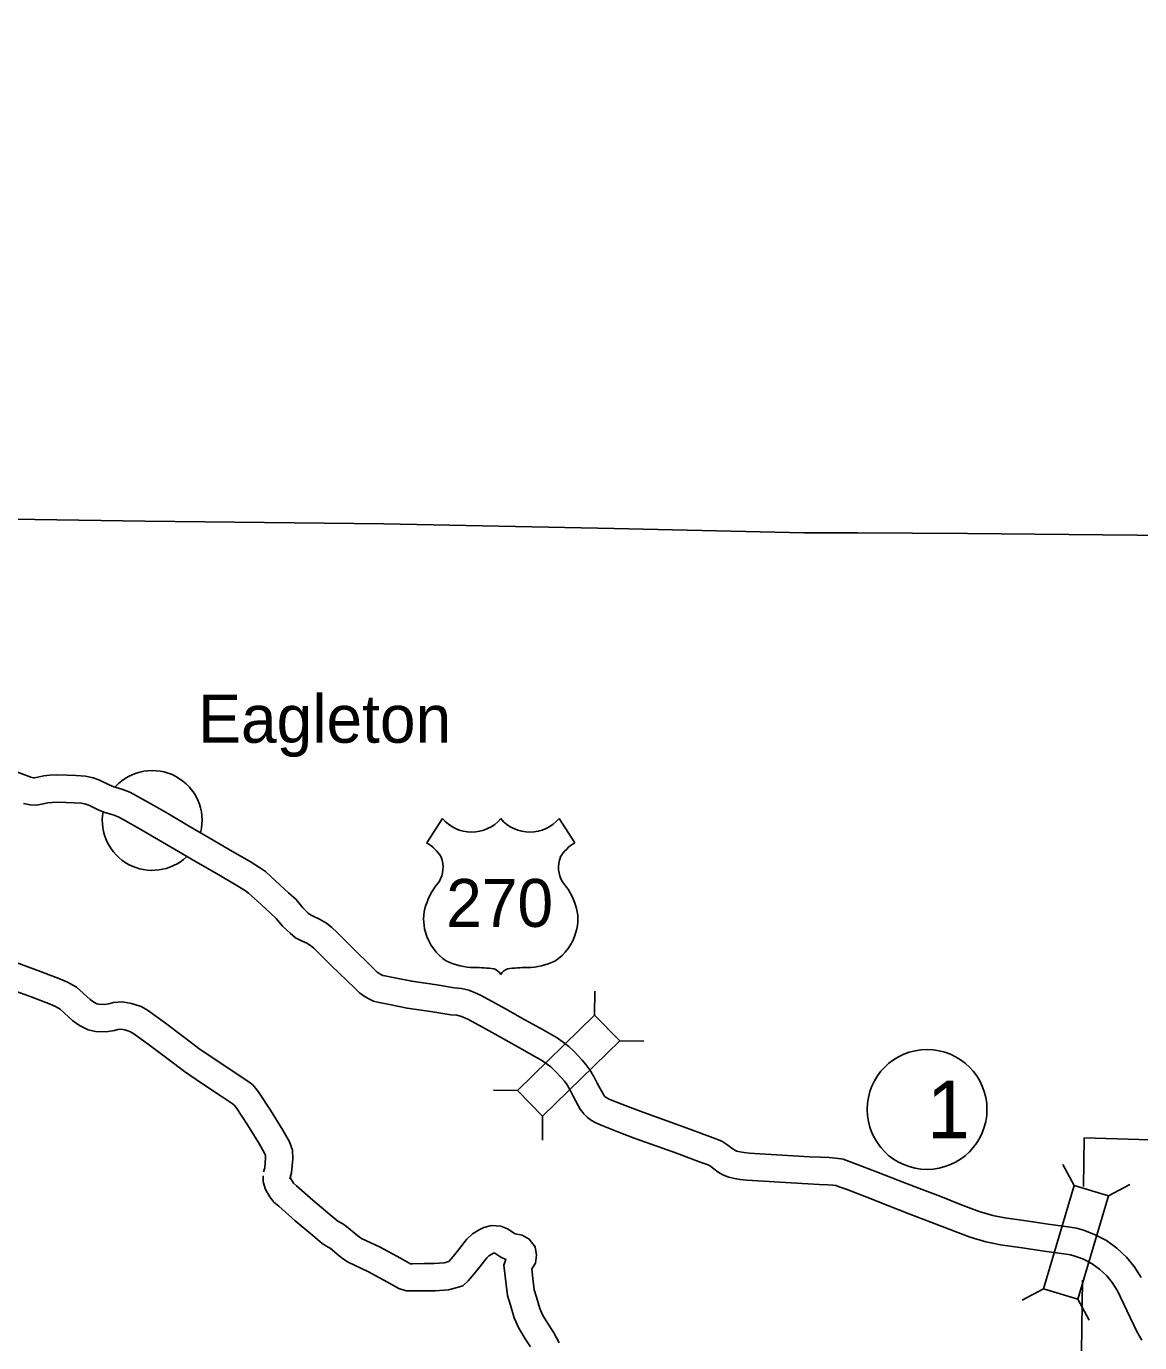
# Model space of a CAD drawing. Extents: x -939622 to -934245, y 1383184 to 1385301.
# Drawn here: x -936388.3 to -936351.49, y 1384181.69 to 1384225.19 of the extents above; entities that cross this region are included whole.
import ezdxf

# ---------------------------------------------------------------- set-up
doc = ezdxf.new("R2010")
doc.units = 0
for name, color, linetype in [('10', 7, 'Continuous'), ('15', 7, 'Continuous'), ('2', 7, 'Continuous'), ('20', 7, 'Continuous'), ('22', 7, 'Continuous'), ('24', 7, 'Continuous'), ('27', 7, 'Continuous'), ('8', 7, 'Continuous'), ('Level 2', 7, 'Continuous')]:
    doc.layers.add(name, color=color, linetype=linetype)

msp = doc.modelspace()

# ---------------------------------------------------------------- linework, layer by layer
at = {"layer": '10'}
for points in [[(-936379.586, 1384187.098), (-936379.528, 1384187.309), (-936379.489, 1384187.767), (-936379.495, 1384188.052), (-936379.602, 1384188.333), (-936379.815, 1384188.709), (-936380.231, 1384189.372), (-936380.63, 1384189.991), (-936380.808, 1384190.208), (-936380.973, 1384190.332), (-936381.326, 1384190.567), (-936382.003, 1384191.019), (-936382.547, 1384191.383), (-936383.069, 1384191.774), (-936383.742, 1384192.286), (-936384.29, 1384192.676), (-936384.5, 1384192.8), (-936384.826, 1384192.905), (-936385.117, 1384192.954), (-936385.418, 1384192.934), (-936385.573, 1384192.891), (-936385.718, 1384192.868), (-936385.906, 1384192.875), (-936385.963, 1384192.886), (-936386.068, 1384192.939), (-936386.193, 1384193.028), (-936386.642, 1384193.441), (-936386.933, 1384193.606), (-936387.168, 1384193.708), (-936387.826, 1384193.96), (-936388.962, 1384194.373)], [(-936380.454, 1384187.335), (-936380.418, 1384187.467), (-936380.39, 1384187.795), (-936380.392, 1384187.877), (-936380.419, 1384187.949), (-936380.588, 1384188.249), (-936380.99, 1384188.889), (-936381.359, 1384189.46), (-936381.435, 1384189.553), (-936381.493, 1384189.597), (-936381.826, 1384189.819), (-936382.504, 1384190.271), (-936383.067, 1384190.649), (-936383.611, 1384191.056), (-936384.275, 1384191.561), (-936384.781, 1384191.921), (-936384.872, 1384191.975), (-936385.039, 1384192.028), (-936385.162, 1384192.049), (-936385.268, 1384192.042), (-936385.382, 1384192.011), (-936385.662, 1384191.965), (-936386.008, 1384191.978), (-936386.257, 1384192.026), (-936386.537, 1384192.168), (-936386.761, 1384192.328), (-936387.175, 1384192.708), (-936387.335, 1384192.799), (-936387.508, 1384192.874), (-936388.142, 1384193.117), (-936389.241, 1384193.517)], [(-936371.636, 1384181.552), (-936371.804, 1384181.817), (-936372.018, 1384182.172), (-936372.17, 1384182.513), (-936372.291, 1384182.935), (-936372.387, 1384183.249), (-936372.445, 1384183.698), (-936372.508, 1384184.252), (-936372.443, 1384184.443), (-936372.609, 1384184.521), (-936372.809, 1384184.651), (-936372.83, 1384184.653), (-936372.85, 1384184.647), (-936372.905, 1384184.62), (-936373.005, 1384184.563), (-936373.079, 1384184.492), (-936373.311, 1384184.197), (-936373.498, 1384183.963), (-936373.694, 1384183.734), (-936373.871, 1384183.568), (-936374.129, 1384183.492), (-936374.347, 1384183.437), (-936374.784, 1384183.407), (-936375.128, 1384183.404), (-936375.535, 1384183.401), (-936375.742, 1384183.404), (-936375.983, 1384183.479), (-936376.36, 1384183.693), (-936377.007, 1384184.041), (-936377.662, 1384184.35), (-936377.813, 1384184.452), (-936377.954, 1384184.556), (-936378.25, 1384184.809), (-936378.315, 1384184.851), (-936378.514, 1384184.971), (-936378.832, 1384185.229), (-936379.411, 1384185.723), (-936379.95, 1384186.197), (-936380.116, 1384186.338), (-936380.25, 1384186.512), (-936380.394, 1384186.757), (-936380.464, 1384187.011), (-936380.47, 1384187.204)], [(-936370.679, 1384181.685), (-936370.862, 1384182.012), (-936371.039, 1384182.291), (-936371.219, 1384182.589), (-936371.322, 1384182.822), (-936371.428, 1384183.19), (-936371.504, 1384183.44), (-936371.552, 1384183.807), (-936371.588, 1384184.128), (-936371.469, 1384184.321), (-936371.432, 1384184.588), (-936371.477, 1384184.863), (-936371.673, 1384185.116), (-936371.904, 1384185.245), (-936372.133, 1384185.292), (-936372.17, 1384185.309), (-936372.396, 1384185.456), (-936372.609, 1384185.54), (-936372.923, 1384185.561), (-936373.172, 1384185.492), (-936373.326, 1384185.416), (-936373.549, 1384185.29), (-936373.749, 1384185.096), (-936374.016, 1384184.757), (-936374.192, 1384184.537), (-936374.335, 1384184.37), (-936374.366, 1384184.36), (-936374.49, 1384184.329), (-936374.819, 1384184.306), (-936375.134, 1384184.304), (-936375.531, 1384184.301), (-936375.599, 1384184.302), (-936375.623, 1384184.31), (-936375.925, 1384184.481), (-936376.602, 1384184.845), (-936377.215, 1384185.134), (-936377.293, 1384185.187), (-936377.393, 1384185.261), (-936377.711, 1384185.532), (-936377.839, 1384185.615), (-936377.995, 1384185.709), (-936378.256, 1384185.921), (-936378.822, 1384186.404), (-936379.361, 1384186.877), (-936379.461, 1384186.962), (-936379.502, 1384187.016), (-936379.558, 1384187.111), (-936379.568, 1384187.146), (-936379.57, 1384187.229)]]:
    msp.add_lwpolyline(points, dxfattribs=at)
at = {"layer": '15'}
for points in [[(-936362.403, 1384187.837), (-936364.401, 1384187.958), (-936364.571, 1384187.975), (-936364.71, 1384187.999), (-936364.81, 1384188.022), (-936364.858, 1384188.04), (-936364.93, 1384188.083), (-936365.022, 1384188.149), (-936365.138, 1384188.244), (-936365.304, 1384188.348), (-936365.504, 1384188.429), (-936365.678, 1384188.49), (-936366.578, 1384188.829), (-936367.888, 1384189.296), (-936368.415, 1384189.501), (-936368.951, 1384189.706), (-936369.056, 1384189.753), (-936369.13, 1384189.797), (-936369.172, 1384189.826), (-936369.187, 1384189.841), (-936369.22, 1384189.888), (-936369.427, 1384190.266), (-936369.529, 1384190.464), (-936369.668, 1384190.707), (-936369.796, 1384190.881), (-936369.918, 1384191.03), (-936370.191, 1384191.31), (-936370.364, 1384191.48), (-936370.538, 1384191.616), (-936370.754, 1384191.763), (-936371.215, 1384192.035), (-936371.815, 1384192.363), (-936372.457, 1384192.725), (-936373.022, 1384193.037), (-936373.283, 1384193.18), (-936373.459, 1384193.258), (-936373.671, 1384193.339), (-936373.914, 1384193.401), (-936374.151, 1384193.423), (-936374.727, 1384193.513), (-936375.555, 1384193.635), (-936376.114, 1384193.746), (-936376.444, 1384193.811), (-936376.513, 1384193.827), (-936376.559, 1384193.85), (-936376.632, 1384193.895), (-936376.698, 1384193.941), (-936376.816, 1384194.058), (-936377.575, 1384194.791), (-936378.027, 1384195.241), (-936378.198, 1384195.407), (-936378.38, 1384195.553), (-936378.602, 1384195.691), (-936378.82, 1384195.787), (-936378.908, 1384195.829), (-936378.976, 1384195.886), (-936379.161, 1384196.067), (-936379.38, 1384196.332), (-936379.627, 1384196.559), (-936380.051, 1384196.943), (-936380.393, 1384197.262), (-936380.562, 1384197.373), (-936380.87, 1384197.569), (-936381.609, 1384198.005), (-936382.251, 1384198.376), (-936382.942, 1384198.776), (-936383.603, 1384199.164), (-936384.062, 1384199.434), (-936384.654, 1384199.762), (-936384.876, 1384199.889), (-936385.141, 1384199.986), (-936385.4, 1384200.063), (-936385.555, 1384200.127), (-936385.896, 1384200.287), (-936386.09, 1384200.353), (-936386.343, 1384200.409), (-936386.662, 1384200.434), (-936386.946, 1384200.445), (-936387.306, 1384200.455), (-936387.517, 1384200.443), (-936387.724, 1384200.42), (-936387.922, 1384200.379), (-936388.026, 1384200.359), (-936388.062, 1384200.36), (-936388.147, 1384200.378), (-936388.292, 1384200.431), (-936389.13, 1384200.745)], [(-936362.457, 1384186.939), (-936364.474, 1384187.061), (-936364.694, 1384187.083), (-936364.885, 1384187.116), (-936365.072, 1384187.158), (-936365.253, 1384187.228), (-936365.422, 1384187.328), (-936365.57, 1384187.434), (-936365.665, 1384187.512), (-936365.716, 1384187.544), (-936365.822, 1384187.587), (-936365.985, 1384187.644), (-936366.888, 1384187.984), (-936368.202, 1384188.453), (-936368.739, 1384188.661), (-936369.297, 1384188.875), (-936369.469, 1384188.952), (-936369.617, 1384189.039), (-936369.744, 1384189.128), (-936369.873, 1384189.251), (-936369.986, 1384189.413), (-936370.222, 1384189.843), (-936370.32, 1384190.034), (-936370.423, 1384190.215), (-936370.507, 1384190.328), (-936370.59, 1384190.43), (-936370.83, 1384190.675), (-936370.959, 1384190.803), (-936371.068, 1384190.888), (-936371.236, 1384191.002), (-936371.66, 1384191.252), (-936372.251, 1384191.576), (-936372.896, 1384191.939), (-936373.456, 1384192.249), (-936373.682, 1384192.373), (-936373.801, 1384192.425), (-936373.944, 1384192.48), (-936374.067, 1384192.511), (-936374.261, 1384192.529), (-936374.862, 1384192.623), (-936375.708, 1384192.748), (-936376.289, 1384192.863), (-936376.631, 1384192.931), (-936376.82, 1384192.973), (-936376.997, 1384193.063), (-936377.128, 1384193.143), (-936377.279, 1384193.251), (-936377.445, 1384193.414), (-936378.205, 1384194.148), (-936378.658, 1384194.599), (-936378.794, 1384194.731), (-936378.902, 1384194.817), (-936379.023, 1384194.893), (-936379.196, 1384194.969), (-936379.402, 1384195.068), (-936379.581, 1384195.219), (-936379.824, 1384195.456), (-936380.035, 1384195.711), (-936380.234, 1384195.895), (-936380.66, 1384196.28), (-936380.951, 1384196.551), (-936381.052, 1384196.618), (-936381.34, 1384196.802), (-936382.063, 1384197.227), (-936382.702, 1384197.598), (-936383.395, 1384197.999), (-936384.059, 1384198.388), (-936384.508, 1384198.653), (-936385.095, 1384198.977), (-936385.257, 1384199.07), (-936385.425, 1384199.132), (-936385.7, 1384199.213), (-936385.918, 1384199.303), (-936386.233, 1384199.451), (-936386.333, 1384199.485), (-936386.476, 1384199.516), (-936386.715, 1384199.535), (-936386.976, 1384199.545), (-936387.293, 1384199.554), (-936387.442, 1384199.546), (-936387.583, 1384199.53), (-936387.744, 1384199.497), (-936387.957, 1384199.455), (-936388.173, 1384199.464), (-936388.394, 1384199.51)], [(-936362.409, 1384187.838), (-936362.046, 1384187.821), (-936361.753, 1384187.807), (-936361.537, 1384187.794), (-936361.294, 1384187.753), (-936361.122, 1384187.686), (-936360.888, 1384187.606), (-936360.19, 1384187.335), (-936359.492, 1384187.061), (-936358.768, 1384186.783), (-936358.069, 1384186.518), (-936357.415, 1384186.262), (-936356.803, 1384186.031), (-936356.349, 1384185.895), (-936356.238, 1384185.871), (-936355.946, 1384185.818), (-936355.246, 1384185.719), (-936354.52, 1384185.611), (-936353.785, 1384185.505), (-936353.582, 1384185.474), (-936353.352, 1384185.405), (-936353.153, 1384185.335), (-936352.987, 1384185.271), (-936352.587, 1384185.071), (-936352.243, 1384184.817), (-936351.924, 1384184.516), (-936351.671, 1384184.212), (-936351.44, 1384183.845)], [(-936362.451, 1384186.939), (-936362.089, 1384186.922), (-936361.801, 1384186.908), (-936361.639, 1384186.898), (-936361.535, 1384186.881), (-936361.431, 1384186.841), (-936361.197, 1384186.76), (-936360.517, 1384186.496), (-936359.817, 1384186.222), (-936359.089, 1384185.942), (-936358.392, 1384185.678), (-936357.738, 1384185.422), (-936357.091, 1384185.178), (-936356.574, 1384185.023), (-936356.415, 1384184.988), (-936356.089, 1384184.929), (-936355.375, 1384184.829), (-936354.651, 1384184.72), (-936353.918, 1384184.615), (-936353.78, 1384184.594), (-936353.632, 1384184.55), (-936353.465, 1384184.49), (-936353.349, 1384184.446), (-936353.059, 1384184.301), (-936352.821, 1384184.125), (-936352.581, 1384183.899), (-936352.401, 1384183.683), (-936352.229, 1384183.409), (-936351.913, 1384182.754), (-936351.58, 1384182.036), (-936351.423, 1384181.77)]]:
    msp.add_lwpolyline(points, dxfattribs=at)
at = {"layer": '2'}
for points in [[(-936362.584, 1384208.458), (-936368.86, 1384208.592), (-936376.474, 1384208.747), (-936384.374, 1384208.84), (-936392.407, 1384208.956), (-936393.024, 1384208.972), (-936392.904, 1384216.908), (-936392.718, 1384224.863), (-936396.731, 1384224.86), (-936404.785, 1384225.099), (-936404.797, 1384225.038), (-936412.856, 1384225.109), (-936419.066, 1384225.193)], [(-936339.272, 1384208.264), (-936341.346, 1384208.289), (-936344.857, 1384208.324), (-936349.277, 1384208.355), (-936352.725, 1384208.387), (-936357.181, 1384208.428), (-936360.823, 1384208.45), (-936362.584, 1384208.458)]]:
    msp.add_lwpolyline(points, dxfattribs=at)
at = {"layer": '20'}
for p, q in [((-936369.51, 1384192.518), (-936369.501, 1384193.31)), ((-936368.68, 1384191.669), (-936367.888, 1384191.659)), ((-936372.059, 1384190.028), (-936372.851, 1384190.037)), ((-936371.229, 1384189.178), (-936371.238, 1384188.386)), ((-936353.656, 1384186.886), (-936354.032, 1384187.583)), ((-936352.518, 1384186.547), (-936351.821, 1384186.923)), ((-936354.675, 1384183.471), (-936355.372, 1384183.094)), ((-936353.536, 1384183.131), (-936353.16, 1384182.435))]:
    msp.add_line(p, q, dxfattribs=at)
for points in [[(-936369.51, 1384192.518), (-936372.059, 1384190.028), (-936371.229, 1384189.178), (-936368.68, 1384191.669)], [(-936353.536, 1384183.131), (-936352.518, 1384186.547), (-936353.656, 1384186.886), (-936354.675, 1384183.471)]]:
    msp.add_lwpolyline(points, close=True, dxfattribs=at)
at = {"layer": '22'}
for p, q in [((-936374.544, 1384199.013), (-936375.063, 1384198.21)), ((-936370.683, 1384199.013), (-936370.164, 1384198.21))]:
    msp.add_line(p, q, dxfattribs=at)
for centre, radius, start, end in [((-936373.577, 1384199.827), 1.264, 220.075, 319.6701), ((-936371.65, 1384199.827), 1.264, 220.3299, 319.925), ((-936375.742, 1384197.045), 1.349, 30.7809, 59.9883), ((-936369.486, 1384197.045), 1.349, 120.0117, 149.2191), ((-936375.445, 1384197.4), 0.925, 328.8105, 21.2108), ((-936369.782, 1384197.4), 0.925, 158.7892, 211.1895), ((-936373.027, 1384195.505), 2.157, 138.9565, 162.6913), ((-936372.201, 1384195.505), 2.157, 17.3087, 41.0435), ((-936373.739, 1384195.681), 1.426, 160.9576, 197.3819), ((-936371.489, 1384195.681), 1.426, 342.6181, 19.0424), ((-936373.507, 1384195.686), 1.65, 195.1074, 237.1312), ((-936371.721, 1384195.686), 1.65, 302.8688, 344.8926), ((-936373.476, 1384196.205), 2.118, 244.0771, 269.5779), ((-936371.751, 1384196.205), 2.118, 270.4221, 295.9229), ((-936373.427, 1384190.208), 3.88, 81.1942, 90.9539), ((-936372.942, 1384193.686), 0.372, 28.0342, 72.9864), ((-936372.285, 1384193.686), 0.372, 107.0136, 151.9658), ((-936371.8, 1384190.208), 3.88, 89.0461, 98.8058)]:
    msp.add_arc(centre, radius, start, end, dxfattribs=at)
at = {"layer": '24'}
for start, end in [(345.9762, 137.3842), (170.0635, 313.4221)]:
    msp.add_arc((-936384.136, 1384198.949), 1.65, start, end, dxfattribs=at)
at = {"layer": '27'}
msp.add_circle((-936358.52, 1384189.399), 1.98, dxfattribs=at)
at = {"layer": '8'}
for points in [[(-936337.339, 1384182.164), (-936337.238, 1384187.969), (-936345.313, 1384188.218), (-936353.322, 1384188.464), (-936353.344, 1384186.85)], [(-936353.386, 1384183.759), (-936353.428, 1384180.621), (-936353.48, 1384172.71), (-936353.508, 1384169.764)]]:
    msp.add_lwpolyline(points, dxfattribs=at)
at = {"layer": 'Level 2'}
for points in [[(-936362.584, 1384208.458), (-936368.86, 1384208.592), (-936376.474, 1384208.747), (-936384.374, 1384208.84), (-936392.407, 1384208.956), (-936393.024, 1384208.972), (-936392.904, 1384216.908), (-936392.718, 1384224.863), (-936396.731, 1384224.86), (-936404.785, 1384225.099), (-936404.797, 1384225.038), (-936412.856, 1384225.109), (-936419.066, 1384225.193)], [(-936339.253, 1384208.264), (-936341.346, 1384208.289), (-936344.857, 1384208.324), (-936349.277, 1384208.355), (-936352.725, 1384208.387), (-936357.181, 1384208.428), (-936360.823, 1384208.45), (-936362.584, 1384208.458)]]:
    msp.add_lwpolyline(points, dxfattribs=at)

# ---------------------------------------------------------------- texts
at = {"layer": '22'}
msp.add_text('270', height=1.584, dxfattribs=at).set_placement((-936374.418, 1384195.432))
at = {"layer": '24'}
msp.add_text('Eagleton', height=1.584, dxfattribs=at).set_placement((-936382.615, 1384201.518))
at = {"layer": '27'}
msp.add_text('1', height=1.901, dxfattribs=at).set_placement((-936358.52, 1384188.449))

doc.saveas('drawing.dxf')
